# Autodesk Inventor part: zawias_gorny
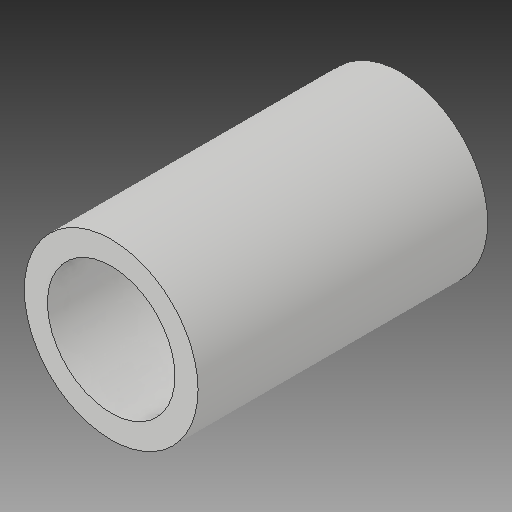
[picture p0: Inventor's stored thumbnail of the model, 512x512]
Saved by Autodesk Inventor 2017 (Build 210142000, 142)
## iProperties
Created: 2020-09
Part Number: zawias_gorny
Material: Generic
Document SubType Name: Modeling
Designer: WindowsX
Density: 1 g/cm^3
Appearance: Default
Mass: 20.1376 g
Surface Area: 88.9071 cm^2
Volume: 20.1376 cm^3
Author: WindowsX
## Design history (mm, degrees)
sketch "Szkic1"
  geometry: C1 r 15 at (0, 0); 1 further point
  constraints: 1 centre point, 1 coincident
  dimensions: "d0" = 30 diameter of C1
extrude "Wyciągnięcie proste1" new body sketch "Szkic1" distance "d1" = 50; taper "d2" = 0 deg
sketch "Szkic2"
  geometry: C1 r 11 at (0, 0); 1 further point
  constraints: 1 centre point, 1 coincident
  dimensions: "d3" = 22 diameter of C1
extrude "Wyciągnięcie proste2" cut sketch "Szkic2" distance "d4" = 40; taper "d5" = 0 deg
node "Bryła1"
